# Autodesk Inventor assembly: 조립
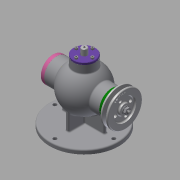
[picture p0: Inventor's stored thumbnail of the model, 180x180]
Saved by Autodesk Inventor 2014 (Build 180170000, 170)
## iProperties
Created: 2020-08
Part Number: 조립
Document SubType Name: Assembly
Designer: kh
Author: kh
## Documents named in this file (18)
- C:\Users\kh\Desktop\700806V1021\조립.iam
- C:\Users\kh\Desktop\700806V1021\본체.ipt
- C:\Users\kh\Desktop\700806V1021\V-벨트풀리.ipt
- C:\Users\kh\Desktop\700806V1021\너트 M8.ipt
- C:\Users\kh\Desktop\700806V1021\뒤커버.ipt
- C:\Users\kh\Desktop\700806V1021\멈춤링 15x1.ipt
- C:\Users\kh\Desktop\700806V1021\멈춤링 35x1.6.ipt
- 멈춤링 35x1.6.ipt
- C:\Users\kh\Desktop\700806V1021\베어링 6202.ipt
- 베어링 6202.ipt
- C:\Users\kh\Desktop\700806V1021\볼트 M4.ipt
- C:\Users\kh\Desktop\700806V1021\상부커버.ipt
- C:\Users\kh\Desktop\700806V1021\슬라이드.ipt
- C:\Users\kh\Desktop\700806V1021\앞커버.ipt
- C:\Users\kh\Desktop\700806V1021\오일 실 15 30 7.ipt
- C:\Users\kh\Desktop\700806V1021\칼라.ipt
- C:\Users\kh\Desktop\700806V1021\키 3x3x12.ipt
- C:\Users\kh\Desktop\700806V1021\편심축.ipt
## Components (1 placed, 1 different names)
1. V-벨트풀리:1 — Insert:16, Mate:1, Insert:17
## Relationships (3: Insert 2, Mate 1)
- Insert:16: V-벨트풀리:1
- Mate:1: V-벨트풀리:1
- Insert:17: V-벨트풀리:1
